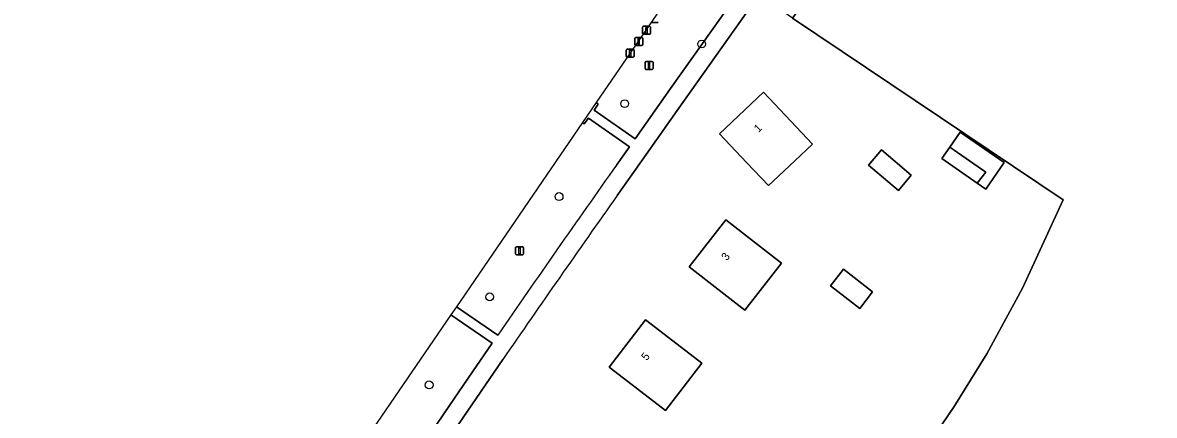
# Model space of a CAD drawing. Extents: x 158793 to 159888, y 384317 to 385256.
# Drawn here: x 159091.5 to 159232.9, y 385080.3 to 385129.3 of the extents above; entities that cross this region are included whole.
import ezdxf

# ---------------------------------------------------------------- set-up
doc = ezdxf.new("R2010")
doc.units = 0
for name, color, linetype in [('IMGEO_Afsluitpaal', 7, 'Continuous'), ('IMGEO_Berm_groen', 7, 'Continuous'), ('IMGEO_Boom', 7, 'Continuous'), ('IMGEO_Erf', 7, 'Continuous'), ('IMGEO_Groenvoorziening', 7, 'Continuous'), ('IMGEO_Hek', 7, 'Continuous'), ('IMGEO_Lichtmast', 7, 'Continuous'), ('IMGEO_Pand', 7, 'Continuous'), ('IMGEO_Pand_nummerreeks', 7, 'Continuous'), ('IMGEO_Voetpad_open', 7, 'Continuous')]:
    doc.layers.add(name, color=color, linetype=linetype)

msp = doc.modelspace()

# ---------------------------------------------------------------- linework, layer by layer
at = {"layer": 'IMGEO_Afsluitpaal'}
for p, q in [((159170.92, 385129.34), (159170.13, 385129.34)), ((159170.13, 385129.34), (159170.92, 385129.34)), ((159168.97, 385127.98), (159168.97, 385128.78)), ((159168.97, 385128.78), (159168.97, 385127.98)), ((159169.07, 385128.88), (159169.86, 385128.88)), ((159169.86, 385128.88), (159169.07, 385128.88)), ((159169.86, 385127.88), (159169.07, 385127.88)), ((159169.07, 385127.88), (159169.86, 385127.88)), ((159169.96, 385128.78), (159169.96, 385127.98)), ((159169.96, 385127.98), (159169.96, 385128.78)), ((159168, 385126.58), (159168, 385127.38)), ((159168, 385127.38), (159168, 385126.58)), ((159168.1, 385127.48), (159168.89, 385127.48)), ((159168.89, 385127.48), (159168.1, 385127.48)), ((159168.89, 385126.48), (159168.1, 385126.48)), ((159168.1, 385126.48), (159168.89, 385126.48)), ((159168.99, 385127.38), (159168.99, 385126.58)), ((159168.99, 385126.58), (159168.99, 385127.38)), ((159166.92, 385125.12), (159166.92, 385125.92)), ((159166.92, 385125.92), (159166.92, 385125.12)), ((159167.02, 385126.02), (159167.81, 385126.02)), ((159167.81, 385126.02), (159167.02, 385126.02)), ((159167.81, 385125.02), (159167.02, 385125.02)), ((159167.02, 385125.02), (159167.81, 385125.02)), ((159167.91, 385125.92), (159167.91, 385125.12)), ((159167.91, 385125.12), (159167.91, 385125.92))]:
    msp.add_line(p, q, dxfattribs=at)
for points in [[(159169.39, 385128.75), (159169.54, 385128.75), (159169.54, 385128), (159169.39, 385128), (159169.39, 385128.75)], [(159168.42, 385127.35), (159168.57, 385127.35), (159168.57, 385126.6), (159168.42, 385126.6), (159168.42, 385127.35)], [(159167.34, 385125.89), (159167.49, 385125.89), (159167.49, 385125.14), (159167.34, 385125.14), (159167.34, 385125.89)]]:
    msp.add_lwpolyline(points, dxfattribs=at)
for centre, start, end in [((159169.07, 385128.78), 90, 180), ((159169.07, 385128.78), 90, 180), ((159169.07, 385127.98), 180, 270), ((159169.07, 385127.98), 180, 270), ((159169.86, 385128.78), 0, 90), ((159169.86, 385128.78), 360, 90), ((159169.86, 385127.98), 270, 0), ((159169.86, 385127.98), 270, 0), ((159168.1, 385127.38), 90, 180), ((159168.1, 385127.38), 90, 180), ((159168.1, 385126.58), 180, 270), ((159168.1, 385126.58), 180, 270), ((159168.89, 385127.38), 0, 90), ((159168.89, 385127.38), 360, 90), ((159168.89, 385126.58), 270, 0), ((159168.89, 385126.58), 270, 0), ((159167.02, 385125.92), 90, 180), ((159167.02, 385125.92), 90, 180), ((159167.02, 385125.12), 180, 270), ((159167.02, 385125.12), 180, 270), ((159167.81, 385125.92), 0, 90), ((159167.81, 385125.92), 360, 90), ((159167.81, 385125.12), 270, 0), ((159167.81, 385125.12), 270, 0)]:
    msp.add_arc(centre, 0.1, start, end, dxfattribs=at)
at = {"layer": 'IMGEO_Berm_groen'}
for points in [[(159234.93, 385202.14), (159231.86, 385199.24), (159227.61, 385203.7), (159224.1, 385200.2), (159222.79, 385198.61), (159227.59, 385194.66), (159212.8, 385176.68), (159207.97, 385180.64), (159205.31, 385177.19), (159205.15, 385177.02), (159201.3, 385172.8), (159190.99, 385159.06), (159183.99, 385149.75), (159183.99, 385149.75), (159163.18, 385119.34)], [(159163.18, 385119.34), (159163.43, 385119.16), (159162.91, 385118.42), (159168.03, 385114.82), (159172.45, 385121.09), (159180.24, 385132.08)], [(159165.72, 385111.54), (159167.33, 385113.82), (159162.22, 385117.42), (159161.69, 385116.7), (159161.48, 385116.86), (159145.71, 385093.8)], [(159145.71, 385093.8), (159150.88, 385090.28)]]:
    msp.add_lwpolyline(points, dxfattribs=at)
msp.add_lwpolyline([(159128.77, 385069.05), (159134, 385065.52), (159144.84, 385081.48), (159147.73, 385085.71), (159150.17, 385089.26), (159145.02, 385092.8)], close=True, dxfattribs=at)
msp.add_arc((160756.63, 383985.39), 1949.16, 144.70659, 145.46869, dxfattribs=at)
at = {"layer": 'IMGEO_Boom'}
for centre in [(159176.36, 385126.67), (159166.74, 385119.21), (159158.54, 385107.6), (159149.86, 385095.06), (159142.3, 385084.06)]:
    msp.add_circle(centre, 0.489, dxfattribs=at)
at = {"layer": 'IMGEO_Erf'}
for points in [[(159148.39, 384946.91), (159153.25, 384941.03), (159150.4, 384957.61), (159141, 384963.54), (159137.02, 384980.94), (159133.84, 384985.25), (159147.59, 384997.37), (159157.45, 385008.13), (159161.83, 385013.79), (159170.02, 385025.49), (159207.92, 385081.38), (159212.01, 385087.95), (159216.48, 385096.14), (159221.55, 385107.19), (159187.72, 385129.9), (159183.54, 385132.81), (159182.12, 385130.8), (159173.31, 385118.35), (159168.14, 385111.04), (159165.8, 385107.73)], [(159151.5, 385087.22), (159146.57, 385079.98), (159135.31, 385063.38), (159135.41, 385063.3), (159118.84, 385038.88), (159111.54, 385028.14), (159091.49, 384998.79), (159092.36, 384995.84), (159103.2, 384987.73), (159110.08, 384982.3), (159117.41, 384976.04), (159118.4, 384977.13), (159120.79, 384975), (159124.18, 384971.91), (159124.28, 384971.82), (159127.17, 384969.19), (159127.35, 384969.38), (159127.3, 384969.43), (159129.77, 384972.03), (159131.93, 384969.99), (159129.46, 384967.37), (159129.34, 384967.23), (159131.49, 384965.09)]]:
    msp.add_lwpolyline(points, dxfattribs=at)
for points in [[(159185.3, 385109.54), (159184.7, 385108.97), (159182.02, 385111.81), (159178.58, 385115.44), (159184.07, 385120.64), (159187.51, 385117.01), (159190.21, 385114.16), (159188, 385112.07)], [(159207.37, 385113.78), (159208.68, 385115.67), (159214.17, 385111.85), (159211.86, 385108.53), (159210.79, 385109.28), (159206.37, 385112.35)], [(159197.21, 385111.52), (159198.82, 385113.43), (159202.56, 385110.28), (159200.96, 385108.37)], [(159178.75, 385095.75), (159174.81, 385098.82), (159179.37, 385104.68), (159183.32, 385101.6), (159186.32, 385099.26), (159181.76, 385093.4)], [(159192.46, 385096.43), (159194.08, 385098.53), (159197.72, 385095.71), (159196.11, 385093.62)], [(159171.83, 385080.87), (159168.76, 385083.23), (159164.8, 385086.28), (159169.35, 385092.2), (159173.31, 385089.15), (159176.38, 385086.79)]]:
    msp.add_lwpolyline(points, close=True, dxfattribs=at)
msp.add_arc((160839.45, 383924.94), 2049.41, 144.75072, 145.44962, dxfattribs=at)
at = {"layer": 'IMGEO_Groenvoorziening'}
msp.add_lwpolyline([(159273.06, 385209.09), (159256.15, 385207.46), (159235.72, 385186.97), (159227.01, 385178.11), (159209.26, 385158.1), (159192.74, 385136.79), (159187.72, 385129.9), (159221.55, 385107.19), (159216.48, 385096.14), (159212.01, 385087.95), (159207.92, 385081.38), (159170.02, 385025.49), (159161.83, 385013.79), (159157.45, 385008.13), (159147.59, 384997.37), (159133.84, 384985.25), (159137.02, 384980.94), (159141, 384963.54), (159150.4, 384957.61), (159153.25, 384941.03), (159155.13, 384938.75), (159161.81, 384930.66), (159170.01, 384919.82)], dxfattribs=at)
at = {"layer": 'IMGEO_Hek'}
msp.add_lwpolyline([(159153.36, 384941.51), (159150.4, 384957.61), (159141, 384963.54), (159137.02, 384980.94), (159133.84, 384985.25), (159147.59, 384997.37), (159157.45, 385008.13), (159161.83, 385013.79), (159170.02, 385025.49), (159207.92, 385081.38), (159212.01, 385087.95), (159216.48, 385096.14), (159221.55, 385107.19), (159187.72, 385129.9), (159192.74, 385136.79), (159209.26, 385158.1), (159227.01, 385178.11), (159235.72, 385186.97)], dxfattribs=at)
at = {"layer": 'IMGEO_Lichtmast'}
for p, q in [((159169.29, 385123.59), (159169.29, 385124.39)), ((159169.29, 385124.39), (159169.29, 385123.59)), ((159169.39, 385124.49), (159170.18, 385124.49)), ((159170.18, 385124.49), (159169.39, 385124.49)), ((159170.18, 385123.49), (159169.39, 385123.49)), ((159169.39, 385123.49), (159170.18, 385123.49)), ((159170.28, 385124.39), (159170.28, 385123.59)), ((159170.28, 385123.59), (159170.28, 385124.39)), ((159153.11, 385100.43), (159153.11, 385101.22)), ((159153.11, 385101.22), (159153.11, 385100.43)), ((159153.21, 385101.32), (159154, 385101.32)), ((159154, 385101.32), (159153.21, 385101.32)), ((159154.1, 385101.22), (159154.1, 385100.43)), ((159154.1, 385100.43), (159154.1, 385101.22)), ((159154, 385100.33), (159153.21, 385100.33)), ((159153.21, 385100.33), (159154, 385100.33))]:
    msp.add_line(p, q, dxfattribs=at)
for points in [[(159169.71, 385124.37), (159169.86, 385124.37), (159169.86, 385123.62), (159169.71, 385123.62), (159169.71, 385124.37)], [(159153.53, 385101.2), (159153.68, 385101.2), (159153.68, 385100.45), (159153.53, 385100.45), (159153.53, 385101.2)]]:
    msp.add_lwpolyline(points, dxfattribs=at)
for centre, start, end in [((159169.39, 385124.39), 90, 180), ((159169.39, 385124.39), 90, 180), ((159169.39, 385123.59), 180, 270), ((159169.39, 385123.59), 180, 270), ((159170.18, 385124.39), 0, 90), ((159170.18, 385124.39), 360, 90), ((159170.18, 385123.59), 270, 0), ((159170.18, 385123.59), 270, 0), ((159153.21, 385101.22), 90, 180), ((159153.21, 385101.22), 90, 180), ((159154, 385101.22), 0, 90), ((159154, 385101.22), 360, 90), ((159153.21, 385100.43), 180, 270), ((159153.21, 385100.43), 180, 270), ((159154, 385100.43), 270, 0), ((159154, 385100.43), 270, 0)]:
    msp.add_arc(centre, 0.1, start, end, dxfattribs=at)
at = {"layer": 'IMGEO_Pand'}
for points in [[(159190.21, 385114.16), (159187.51, 385117.01), (159184.07, 385120.64), (159178.58, 385115.44), (159182.02, 385111.81), (159184.7, 385108.97), (159185.3, 385109.54), (159188, 385112.07)], [(159210.79, 385109.28), (159211.86, 385108.53), (159214.17, 385111.85), (159208.68, 385115.67), (159207.37, 385113.78), (159211.89, 385110.67)], [(159211.89, 385110.67), (159207.37, 385113.78), (159206.37, 385112.35), (159210.79, 385109.28)], [(159202.56, 385110.28), (159198.82, 385113.43), (159197.21, 385111.52), (159200.96, 385108.37)], [(159178.75, 385095.75), (159181.76, 385093.4), (159186.32, 385099.26), (159183.32, 385101.6), (159179.37, 385104.68), (159174.81, 385098.82)], [(159192.46, 385096.43), (159196.11, 385093.62), (159197.72, 385095.71), (159194.08, 385098.53)], [(159168.76, 385083.23), (159171.83, 385080.87), (159176.38, 385086.79), (159173.31, 385089.15), (159169.35, 385092.2), (159164.8, 385086.28)]]:
    msp.add_lwpolyline(points, close=True, dxfattribs=at)
at = {"layer": 'IMGEO_Voetpad_open'}
for points in [[(159180.24, 385132.08), (159172.45, 385121.09), (159168.03, 385114.82), (159162.91, 385118.42), (159163.43, 385119.16), (159163.18, 385119.34), (159161.48, 385116.86), (159161.69, 385116.7), (159162.22, 385117.42), (159167.33, 385113.82), (159165.72, 385111.54)], [(159165.8, 385107.73), (159168.14, 385111.04), (159173.31, 385118.35), (159182.12, 385130.8), (159183.54, 385132.81)], [(159150.88, 385090.28), (159145.71, 385093.8), (159145.02, 385092.8), (159150.17, 385089.26), (159147.73, 385085.71), (159144.84, 385081.48), (159134, 385065.52)], [(159131.49, 384965.09), (159129.34, 384967.23), (159129.46, 384967.37), (159127.35, 384969.38), (159127.17, 384969.19), (159124.28, 384971.82), (159124.18, 384971.91), (159120.79, 384975), (159118.4, 384977.13), (159117.41, 384976.04), (159110.08, 384982.3), (159103.2, 384987.73), (159092.36, 384995.84), (159091.49, 384998.79), (159111.54, 385028.14), (159118.84, 385038.88), (159135.41, 385063.3), (159135.31, 385063.38), (159146.57, 385079.98), (159151.5, 385087.22)]]:
    msp.add_lwpolyline(points, dxfattribs=at)
for centre, radius, start, end in [((160756.63, 383985.39), 1949.16, 144.70659, 145.46869), ((160839.45, 383924.94), 2049.41, 144.75072, 145.44962)]:
    msp.add_arc(centre, radius, start, end, dxfattribs=at)

# ---------------------------------------------------------------- texts
at = {"layer": 'IMGEO_Pand_nummerreeks'}
for s, rotation, p in [('1', 43.4417, (159183.46, 385115.55)), ('3', 52.0512, (159179.51, 385099.52)), ('5', 52.4422, (159169.5, 385087.02))]:
    msp.add_text(s, height=1, rotation=rotation, dxfattribs=at).set_placement(p)

doc.saveas('drawing.dxf')
